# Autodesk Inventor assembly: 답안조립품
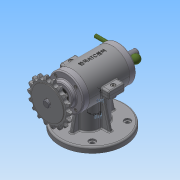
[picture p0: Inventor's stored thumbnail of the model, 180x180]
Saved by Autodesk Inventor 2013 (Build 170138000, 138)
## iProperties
Created: 2016-04
Part Number: 답안조립품
Document SubType Name: Assembly
Designer: Administrator
Author: Administrator
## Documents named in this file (19)
- C:\Users\Administrator\Desktop\360408V1019\답안조립품.iam
- C:\Users\Administrator\Desktop\360408V1019\본체.ipt
- C:\Users\Administrator\Desktop\360408V1019\베어링 6201.ipt
- C:\Users\Administrator\Desktop\360408V1019\베어링 6202.ipt
- C:\Users\Administrator\Desktop\360408V1019\편심축.ipt
- C:\Users\Administrator\Desktop\360408V1019\뒤커버.ipt
- C:\Users\Administrator\Desktop\360408V1019\앞커버.ipt
- C:\Users\Administrator\Desktop\360408V1019\슬라이드.ipt
- C:\Users\Administrator\Desktop\360408V1019\스프링.ipt
- C:\Users\Administrator\Desktop\360408V1019\본체상부커버.ipt
- C:\Users\Administrator\Desktop\360408V1019\오일실 12 22 7.ipt
- C:\Users\Administrator\Desktop\360408V1019\볼트 M3x0.5x8.ipt
- C:\Users\Administrator\Desktop\360408V1019\스프로킷.ipt
- C:\Users\Administrator\Desktop\360408V1019\키 4 x 4 x 18.ipt
- C:\Users\Administrator\Desktop\360408V1019\멈춤나사 M3x8.ipt
- C:\Users\Administrator\Desktop\360408V1019\볼트 M4 x 16.ipt
- C:\Users\Administrator\Desktop\360408V1019\너트 M4.ipt
- C:\Users\Administrator\Desktop\360408V1019\와셔 ST 4-100.ipt
- C:\Users\Administrator\Desktop\360408V1019\레바.ipt
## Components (6 placed, 3 different names)
1. ISO 4762 M4 x 16:1
2. ISO 4762 M4 x 16:2
3. ISO 4032 M4:1
4. ISO 4032 M4:2
5. ISO 7091 ST 4 - 100 HV:1
6. ISO 7091 ST 4 - 100 HV:2
